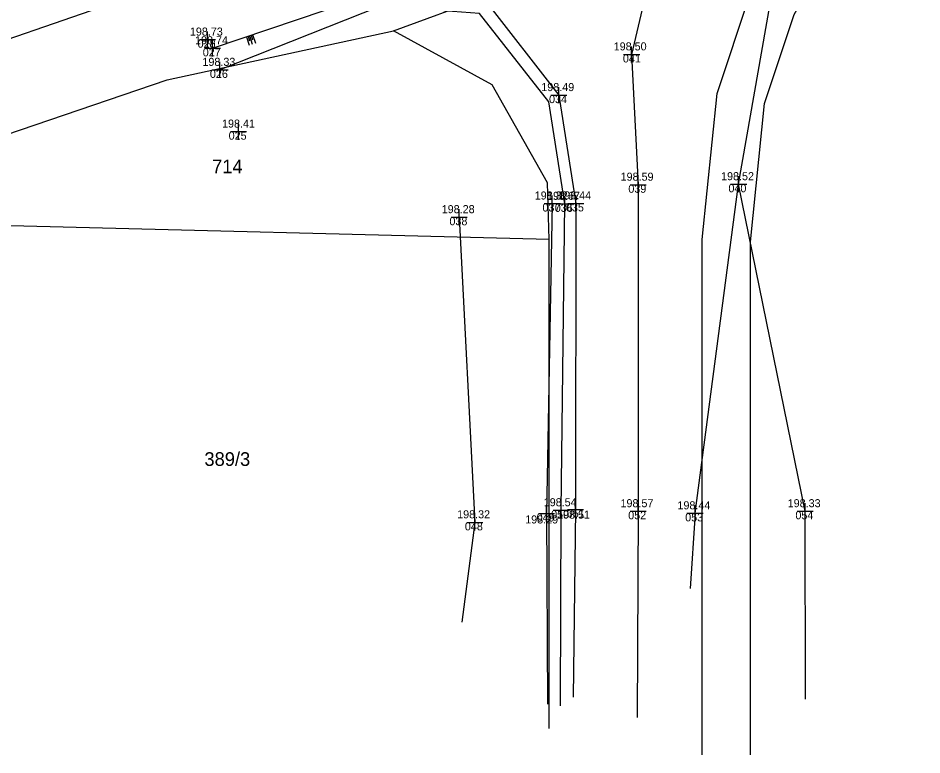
# Model space of a CAD drawing. Extents: x -706655 to -706193, y -1036183 to -1034979.
# Drawn here: x -706443.5 to -706387.4, y -1035267.3 to -1035221.5 of the extents above; entities that cross this region are included whole.
import ezdxf

# ---------------------------------------------------------------- set-up
doc = ezdxf.new("R2010")
doc.units = 0
for name, color, linetype in [('Hranice parcel', 7, 'Continuous'), ('křížky', 7, 'Continuous'), ('Parcelní čísla', 7, 'Continuous'), ('Stávající terén', 7, 'Continuous'), ('výšky', 7, 'Continuous'), ('čísla bodu', 7, 'Continuous')]:
    doc.layers.add(name, color=color, linetype=linetype)

msp = doc.modelspace()

# ---------------------------------------------------------------- linework, layer by layer
at = {"layer": 'Hranice parcel'}
for p, q in [((-706420.22, -1035222.31), (-706388.41, -1035210.6)), ((-706475.168, -1035233.522), (-706432.87, -1035218.92)), ((-706410.54, -1035235.29), (-706459.76, -1035234.05)), ((-706410.54, -1035265.68), (-706410.54, -1035235.29))]:
    msp.add_line(p, q, dxfattribs=at)
for points in [[(-706401.04, -1035267.33), (-706401.04, -1035235.29), (-706400.11, -1035226.21), (-706398.07, -1035220.07), (-706394.74, -1035214.25), (-706388.41, -1035210.6)], [(-706398.04, -1035267.33), (-706398.04, -1035235.44), (-706397.16, -1035226.84), (-706395.32, -1035221.3), (-706392.54, -1035216.45), (-706387.38, -1035213.42)], [(-706459.76, -1035234.05), (-706434.28, -1035225.37), (-706420.22, -1035222.31)], [(-706410.54, -1035235.29), (-706410.64, -1035231.77), (-706414.08, -1035225.67), (-706420.22, -1035222.31)]]:
    msp.add_lwpolyline(points, dxfattribs=at)
at = {"layer": 'křížky'}
for p, q in [((-706431.78, -1035223.36), (-706431.78, -1035222.36)), ((-706432.28, -1035222.86), (-706431.28, -1035222.86)), ((-706431.78, -1035222.86), (-706431.78, -1035222.86)), ((-706431.46, -1035223.9), (-706431.46, -1035222.9)), ((-706431.96, -1035223.4), (-706430.96, -1035223.4)), ((-706431.46, -1035223.4), (-706431.46, -1035223.4)), ((-706405.42, -1035224.28), (-706405.42, -1035223.28)), ((-706405.92, -1035223.78), (-706404.92, -1035223.78)), ((-706405.42, -1035223.78), (-706405.42, -1035223.78)), ((-706431, -1035225.24), (-706431, -1035224.24)), ((-706431.5, -1035224.74), (-706430.5, -1035224.74)), ((-706431, -1035224.74), (-706431, -1035224.74)), ((-706410.44, -1035226.31), (-706409.44, -1035226.31)), ((-706409.94, -1035226.81), (-706409.94, -1035225.81)), ((-706409.94, -1035226.31), (-706409.94, -1035226.31)), ((-706429.85, -1035229.08), (-706429.85, -1035228.08)), ((-706430.35, -1035228.58), (-706429.35, -1035228.58)), ((-706429.85, -1035228.58), (-706429.85, -1035228.58)), ((-706398.77, -1035232.35), (-706398.77, -1035231.35)), ((-706405.51, -1035231.88), (-706404.51, -1035231.88)), ((-706405.01, -1035232.38), (-706405.01, -1035231.38)), ((-706405.01, -1035231.88), (-706405.01, -1035231.88)), ((-706399.27, -1035231.85), (-706398.27, -1035231.85)), ((-706398.77, -1035231.85), (-706398.77, -1035231.85)), ((-706410.85, -1035233.05), (-706409.85, -1035233.05)), ((-706410.35, -1035233.55), (-706410.35, -1035232.55)), ((-706410.35, -1035233.05), (-706410.35, -1035233.05)), ((-706409.57, -1035233.57), (-706409.57, -1035232.57)), ((-706409.39, -1035233.04), (-706408.39, -1035233.04)), ((-706408.89, -1035233.54), (-706408.89, -1035232.54)), ((-706408.89, -1035233.04), (-706408.89, -1035233.04)), ((-706416.13, -1035234.4), (-706416.13, -1035233.4)), ((-706410.07, -1035233.07), (-706409.07, -1035233.07)), ((-706409.57, -1035233.07), (-706409.57, -1035233.07)), ((-706416.63, -1035233.9), (-706415.63, -1035233.9)), ((-706416.13, -1035233.9), (-706416.13, -1035233.9)), ((-706408.91, -1035252.57), (-706408.91, -1035251.57)), ((-706410.71, -1035252.82), (-706410.71, -1035251.82)), ((-706410.29, -1035252.12), (-706409.29, -1035252.12)), ((-706409.79, -1035252.62), (-706409.79, -1035251.62)), ((-706409.79, -1035252.12), (-706409.79, -1035252.12)), ((-706409.41, -1035252.07), (-706408.41, -1035252.07)), ((-706408.91, -1035252.07), (-706408.91, -1035252.07)), ((-706405.02, -1035252.68), (-706405.02, -1035251.68)), ((-706401.48, -1035252.81), (-706401.48, -1035251.81)), ((-706394.63, -1035252.68), (-706394.63, -1035251.68)), ((-706415.17, -1035253.37), (-706415.17, -1035252.37)), ((-706411.21, -1035252.32), (-706410.21, -1035252.32)), ((-706410.71, -1035252.32), (-706410.71, -1035252.32)), ((-706405.52, -1035252.18), (-706404.52, -1035252.18)), ((-706405.02, -1035252.18), (-706405.02, -1035252.18)), ((-706401.98, -1035252.31), (-706400.98, -1035252.31)), ((-706401.48, -1035252.31), (-706401.48, -1035252.31)), ((-706395.13, -1035252.18), (-706394.13, -1035252.18)), ((-706394.63, -1035252.18), (-706394.63, -1035252.18)), ((-706415.67, -1035252.87), (-706414.67, -1035252.87)), ((-706415.17, -1035252.87), (-706415.17, -1035252.87))]:
    msp.add_line(p, q, dxfattribs=at)
at = {"layer": 'Stávající terén'}
for p, q in [((-706429.347, -1035222.679), (-706429.186, -1035223.201)), ((-706429.252, -1035222.645), (-706429.166, -1035222.927)), ((-706429.158, -1035222.612), (-706428.995, -1035223.142)), ((-706429.064, -1035222.578), (-706428.975, -1035222.868)), ((-706428.97, -1035222.544), (-706428.804, -1035223.084)), ((-706401.48, -1035252.31), (-706398.77, -1035231.85)), ((-706394.63, -1035252.18), (-706398.77, -1035231.85))]:
    msp.add_line(p, q, dxfattribs=at)
for points in [[(-706394.17, -1035209.4), (-706400.57, -1035213.32), (-706404.16, -1035218.4), (-706405.42, -1035223.78), (-706405.01, -1035231.88), (-706405.02, -1035252.18), (-706405.074, -1035265.009)], [(-706398.77, -1035231.85), (-706396.81, -1035220.63), (-706395.67, -1035216.55), (-706391.1, -1035214.26)], [(-706431.46, -1035223.4), (-706420.96, -1035219.82), (-706414.52, -1035220.43), (-706409.94, -1035226.31), (-706408.89, -1035233.04), (-706408.91, -1035252.07), (-706409.059, -1035263.746)], [(-706409.831, -1035264.273), (-706409.79, -1035252.12), (-706409.57, -1035233.07), (-706410.57, -1035226.73), (-706414.87, -1035221.23), (-706421.03, -1035220.77), (-706431, -1035224.74)], [(-706410.35, -1035233.05), (-706410.71, -1035252.32), (-706410.644, -1035264.17)], [(-706416.13, -1035233.9), (-706415.17, -1035252.87), (-706415.98, -1035259.084)], [(-706401.48, -1035252.31), (-706401.786, -1035256.982)], [(-706394.618, -1035263.861), (-706394.63, -1035252.18)]]:
    msp.add_lwpolyline(points, dxfattribs=at)
at = {"layer": 'čísla bodu'}
for p, q in [((-706431.78, -1035223.36), (-706431.78, -1035222.36)), ((-706432.28, -1035222.86), (-706431.28, -1035222.86)), ((-706431.78, -1035222.86), (-706431.78, -1035222.86)), ((-706431.46, -1035223.9), (-706431.46, -1035222.9)), ((-706431.96, -1035223.4), (-706430.96, -1035223.4)), ((-706431.46, -1035223.4), (-706431.46, -1035223.4)), ((-706405.42, -1035224.28), (-706405.42, -1035223.28)), ((-706405.92, -1035223.78), (-706404.92, -1035223.78)), ((-706405.42, -1035223.78), (-706405.42, -1035223.78)), ((-706431, -1035225.24), (-706431, -1035224.24)), ((-706431.5, -1035224.74), (-706430.5, -1035224.74)), ((-706431, -1035224.74), (-706431, -1035224.74)), ((-706410.44, -1035226.31), (-706409.44, -1035226.31)), ((-706409.94, -1035226.81), (-706409.94, -1035225.81)), ((-706409.94, -1035226.31), (-706409.94, -1035226.31)), ((-706429.85, -1035229.08), (-706429.85, -1035228.08)), ((-706430.35, -1035228.58), (-706429.35, -1035228.58)), ((-706429.85, -1035228.58), (-706429.85, -1035228.58)), ((-706398.77, -1035232.35), (-706398.77, -1035231.35)), ((-706405.51, -1035231.88), (-706404.51, -1035231.88)), ((-706405.01, -1035232.38), (-706405.01, -1035231.38)), ((-706405.01, -1035231.88), (-706405.01, -1035231.88)), ((-706399.27, -1035231.85), (-706398.27, -1035231.85)), ((-706398.77, -1035231.85), (-706398.77, -1035231.85)), ((-706410.85, -1035233.05), (-706409.85, -1035233.05)), ((-706410.35, -1035233.55), (-706410.35, -1035232.55)), ((-706410.35, -1035233.05), (-706410.35, -1035233.05)), ((-706409.57, -1035233.57), (-706409.57, -1035232.57)), ((-706409.39, -1035233.04), (-706408.39, -1035233.04)), ((-706408.89, -1035233.54), (-706408.89, -1035232.54)), ((-706408.89, -1035233.04), (-706408.89, -1035233.04)), ((-706416.13, -1035234.4), (-706416.13, -1035233.4)), ((-706410.07, -1035233.07), (-706409.07, -1035233.07)), ((-706409.57, -1035233.07), (-706409.57, -1035233.07)), ((-706416.63, -1035233.9), (-706415.63, -1035233.9)), ((-706416.13, -1035233.9), (-706416.13, -1035233.9)), ((-706408.91, -1035252.57), (-706408.91, -1035251.57)), ((-706410.71, -1035252.82), (-706410.71, -1035251.82)), ((-706410.29, -1035252.12), (-706409.29, -1035252.12)), ((-706409.79, -1035252.62), (-706409.79, -1035251.62)), ((-706409.79, -1035252.12), (-706409.79, -1035252.12)), ((-706409.41, -1035252.07), (-706408.41, -1035252.07)), ((-706408.91, -1035252.07), (-706408.91, -1035252.07)), ((-706405.02, -1035252.68), (-706405.02, -1035251.68)), ((-706401.48, -1035252.81), (-706401.48, -1035251.81)), ((-706394.63, -1035252.68), (-706394.63, -1035251.68)), ((-706415.17, -1035253.37), (-706415.17, -1035252.37)), ((-706411.21, -1035252.32), (-706410.21, -1035252.32)), ((-706410.71, -1035252.32), (-706410.71, -1035252.32)), ((-706405.52, -1035252.18), (-706404.52, -1035252.18)), ((-706405.02, -1035252.18), (-706405.02, -1035252.18)), ((-706401.98, -1035252.31), (-706400.98, -1035252.31)), ((-706401.48, -1035252.31), (-706401.48, -1035252.31)), ((-706395.13, -1035252.18), (-706394.13, -1035252.18)), ((-706394.63, -1035252.18), (-706394.63, -1035252.18)), ((-706415.67, -1035252.87), (-706414.67, -1035252.87)), ((-706415.17, -1035252.87), (-706415.17, -1035252.87))]:
    msp.add_line(p, q, dxfattribs=at)

# ---------------------------------------------------------------- texts
at = {"layer": 'Parcelní čísla'}
for s, p in [('714', (-706431.492, -1035231.169)), ('389/3', (-706431.967, -1035249.36))]:
    msp.add_text(s, height=0.85, dxfattribs=at).set_placement(p)
at = {"layer": 'výšky'}
for s, p in [('198.73', (-706432.872, -1035222.61)), ('198.74', (-706432.552, -1035223.15)), ('198.50', (-706406.534, -1035223.53)), ('198.33', (-706432.092, -1035224.49)), ('198.49', (-706411.034, -1035226.06)), ('198.41', (-706430.873, -1035228.33)), ('198.59', (-706406.104, -1035231.63)), ('198.52', (-706399.862, -1035231.6)), ('198.32', (-706411.442, -1035232.8)), ('198.67', (-706410.676, -1035232.82)), ('198.44', (-706409.982, -1035232.79)), ('198.28', (-706417.222, -1035233.65)), ('198.54', (-706410.882, -1035251.87)), ('198.57', (-706406.112, -1035251.93)), ('198.44', (-706402.572, -1035252.06)), ('198.33', (-706395.722, -1035251.93)), ('198.32', (-706416.262, -1035252.62)), ('198.51', (-706410.053, -1035252.64)), ('198.29', (-706412.034, -1035252.94))]:
    msp.add_text(s, height=0.5, dxfattribs=at).set_placement(p)
at = {"layer": 'čísla bodu'}
for s, p in [('028', (-706432.392, -1035223.36)), ('027', (-706432.072, -1035223.9)), ('041', (-706405.962, -1035224.28)), ('026', (-706431.626, -1035225.24)), ('034', (-706410.552, -1035226.81)), ('025', (-706430.462, -1035229.08)), ('039', (-706405.624, -1035232.38)), ('040', (-706399.404, -1035232.35)), ('037', (-706410.962, -1035233.55)), ('035', (-706409.502, -1035233.54)), ('036', (-706410.196, -1035233.57)), ('038', (-706416.742, -1035234.4)), ('050', (-706410.424, -1035252.62)), ('051', (-706409.452, -1035252.57)), ('049', (-706411.324, -1035252.82)), ('052', (-706405.632, -1035252.68)), ('053', (-706402.092, -1035252.81)), ('054', (-706395.242, -1035252.68)), ('048', (-706415.782, -1035253.37))]:
    msp.add_text(s, height=0.5, dxfattribs=at).set_placement(p)

doc.saveas('drawing.dxf')
